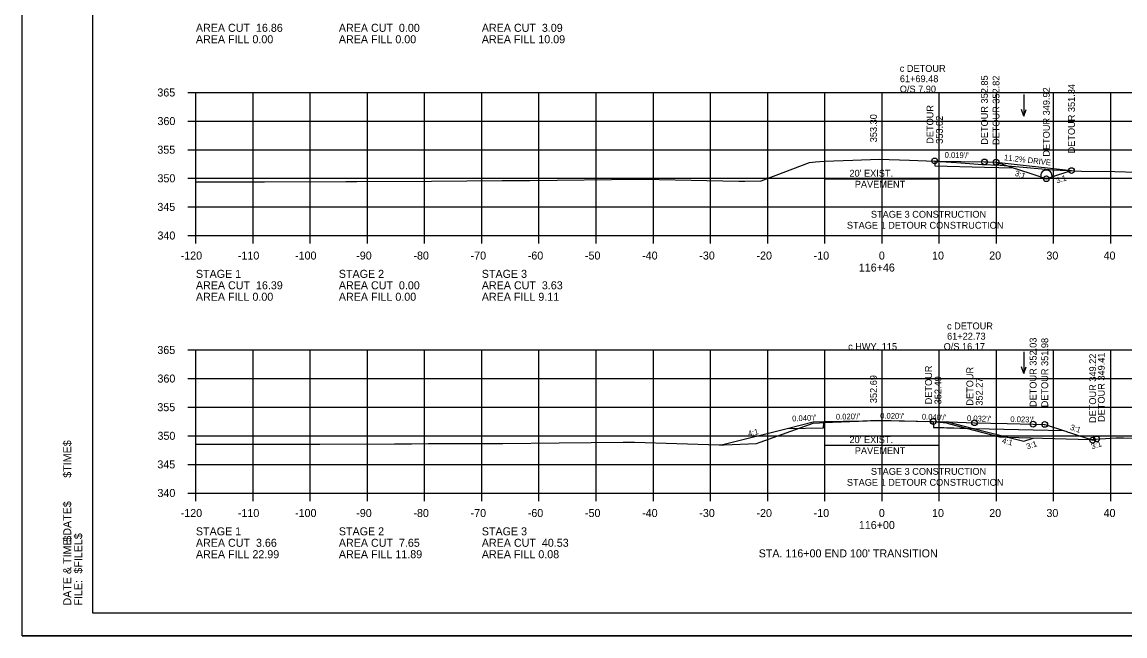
# Model space of a CAD drawing. Extents: x 1630712 to 1632516, y 782146 to 785403.
# Drawn here: x 1632182.6 to 1632375.4, y 785190 to 785297.3 of the extents above; entities that cross this region are included whole.
import ezdxf

# ---------------------------------------------------------------- set-up
doc = ezdxf.new("R2010")
doc.units = 0
for name, color, linetype in [('Default', 7, 'Continuous'), ('Notes', 7, 'Continuous'), ('R_Alt Surface', 7, 'Continuous'), ('R_Annot', 7, 'Continuous'), ('R_Axis', 7, 'Continuous'), ('R_Axis Annot', 7, 'Continuous'), ('R_Border', 7, 'Continuous'), ('R_Detour Subgrade', 7, 'Continuous'), ('R_Detour Surface', 7, 'Continuous'), ('R_Exist Surface', 7, 'Continuous'), ('R_Fin Surface', 7, 'Continuous'), ('R_Grid', 7, 'Continuous'), ('R_No Plot', 7, 'Continuous'), ('R_Water Annot', 7, 'Continuous'), ('R_Xsect Elev', 7, 'Continuous'), ('R_Xsect Elev Detour', 7, 'Continuous'), ('R_Xsect Slope', 7, 'Continuous')]:
    doc.layers.add(name, color=color, linetype=linetype)

msp = doc.modelspace()

# ---------------------------------------------------------------- linework, layer by layer
at = {"layer": 'Default'}
for centre, radius, start, end in [((1632361.69, 785270.42), 0.995, 356.5785, 183.4215), ((1632361.1, 785270.38), 0.412, 183.4215, 256.4158), ((1632362.27, 785270.38), 0.412, 283.5842, 356.5785), ((1632361.69, 785272.79), 2.89, 256.4158, 283.5842)]:
    msp.add_arc(centre, radius, start, end, dxfattribs=at)
at = {"layer": 'Notes'}
for p, q in [((1632322.96, 785268.2), (1632322.96, 785271.6)), ((1632342.96, 785268.2), (1632342.96, 785271.6)), ((1632322.96, 785269.9), (1632342.96, 785269.9)), ((1632322.96, 785221.64), (1632322.96, 785225.04)), ((1632342.96, 785221.64), (1632342.96, 785225.04)), ((1632322.96, 785223.34), (1632342.96, 785223.34))]:
    msp.add_line(p, q, dxfattribs=at)
at = {"layer": 'R_Alt Surface'}
msp.add_lwpolyline([(1632316.37, 785226.27), (1632322.7, 785226.39), (1632322.75, 785227.3), (1632330.92, 785227.64), (1632332.96, 785227.68), (1632341.91, 785227.48), (1632341.96, 785226.42), (1632348.87, 785226.28)], dxfattribs=at)
at = {"layer": 'R_Axis'}
for p, q in [((1632211.56, 785284.98), (1632212.96, 785284.98)), ((1632212.96, 785259.98), (1632212.96, 785284.98)), ((1632211.56, 785279.98), (1632212.96, 785279.98)), ((1632211.56, 785274.98), (1632212.96, 785274.98)), ((1632211.56, 785269.98), (1632212.96, 785269.98)), ((1632211.56, 785264.98), (1632212.96, 785264.98)), ((1632211.56, 785259.98), (1632212.96, 785259.98)), ((1632212.96, 785259.98), (1632492.96, 785259.98)), ((1632212.96, 785258.58), (1632212.96, 785259.98)), ((1632222.96, 785258.58), (1632222.96, 785259.98)), ((1632232.96, 785258.58), (1632232.96, 785259.98)), ((1632242.96, 785258.58), (1632242.96, 785259.98)), ((1632252.96, 785258.58), (1632252.96, 785259.98)), ((1632262.96, 785258.58), (1632262.96, 785259.98)), ((1632272.96, 785258.58), (1632272.96, 785259.98)), ((1632282.96, 785258.58), (1632282.96, 785259.98)), ((1632292.96, 785258.58), (1632292.96, 785259.98)), ((1632302.96, 785258.58), (1632302.96, 785259.98)), ((1632312.96, 785258.58), (1632312.96, 785259.98)), ((1632322.96, 785258.58), (1632322.96, 785259.98)), ((1632332.96, 785258.58), (1632332.96, 785259.98)), ((1632342.96, 785258.58), (1632342.96, 785259.98)), ((1632352.96, 785258.58), (1632352.96, 785259.98)), ((1632362.96, 785258.58), (1632362.96, 785259.98)), ((1632372.96, 785258.58), (1632372.96, 785259.98)), ((1632211.56, 785239.98), (1632212.96, 785239.98)), ((1632212.96, 785214.98), (1632212.96, 785239.98)), ((1632211.56, 785234.98), (1632212.96, 785234.98)), ((1632211.56, 785229.98), (1632212.96, 785229.98)), ((1632211.56, 785224.98), (1632212.96, 785224.98)), ((1632211.56, 785219.98), (1632212.96, 785219.98)), ((1632211.56, 785214.98), (1632212.96, 785214.98)), ((1632212.96, 785214.98), (1632492.96, 785214.98)), ((1632212.96, 785213.58), (1632212.96, 785214.98)), ((1632222.96, 785213.58), (1632222.96, 785214.98)), ((1632232.96, 785213.58), (1632232.96, 785214.98)), ((1632242.96, 785213.58), (1632242.96, 785214.98)), ((1632252.96, 785213.58), (1632252.96, 785214.98)), ((1632262.96, 785213.58), (1632262.96, 785214.98)), ((1632272.96, 785213.58), (1632272.96, 785214.98)), ((1632282.96, 785213.58), (1632282.96, 785214.98)), ((1632292.96, 785213.58), (1632292.96, 785214.98)), ((1632302.96, 785213.58), (1632302.96, 785214.98)), ((1632312.96, 785213.58), (1632312.96, 785214.98)), ((1632322.96, 785213.58), (1632322.96, 785214.98)), ((1632332.96, 785213.58), (1632332.96, 785214.98)), ((1632342.96, 785213.58), (1632342.96, 785214.98)), ((1632352.96, 785213.58), (1632352.96, 785214.98)), ((1632362.96, 785213.58), (1632362.96, 785214.98)), ((1632372.96, 785213.58), (1632372.96, 785214.98))]:
    msp.add_line(p, q, dxfattribs=at)
at = {"layer": 'R_Border'}
for p, q in [((1632194.96, 785193.98), (1632194.96, 785399.44)), ((1632511.14, 785193.98), (1632194.96, 785193.98))]:
    msp.add_line(p, q, dxfattribs=at)
at = {"layer": 'R_Detour Subgrade'}
for points in [[(1632342.16, 785273.01), (1632342.17, 785272.13), (1632350.87, 785271.94), (1632355.86, 785271.82)], [(1632342.16, 785273.01), (1632342.17, 785272.13), (1632350.87, 785271.94), (1632355.86, 785271.82)], [(1632341.91, 785227.48), (1632341.96, 785226.48), (1632349.13, 785226.25), (1632359.37, 785226.01), (1632364.68, 785225.89)], [(1632341.91, 785227.48), (1632341.96, 785226.48), (1632349.13, 785226.25), (1632359.37, 785226.01), (1632364.68, 785225.89)]]:
    msp.add_lwpolyline(points, dxfattribs=at)
at = {"layer": 'R_Detour Surface'}
msp.add_line((1632352.89, 785272.8), (1632366.08, 785271.33), dxfattribs=at)
for points in [[(1632342.16, 785273.01), (1632342.16, 785273.01), (1632342.58, 785273), (1632350.87, 785272.84), (1632351.39, 785272.83), (1632352.89, 785272.8), (1632354.74, 785272.19), (1632355.86, 785271.82), (1632356.24, 785271.7), (1632356.47, 785271.62), (1632359.33, 785270.68), (1632361.69, 785269.9), (1632363.55, 785270.51), (1632366.07, 785271.33)], [(1632341.91, 785227.48), (1632344.71, 785227.39), (1632349.12, 785227.25), (1632349.12, 785227.25), (1632349.13, 785227.25), (1632354.84, 785227.12), (1632359.37, 785227.01), (1632361.33, 785226.96), (1632361.41, 785226.96), (1632361.82, 785226.83), (1632364.68, 785225.89), (1632365.25, 785225.7), (1632365.3, 785225.68), (1632365.73, 785225.54), (1632369.79, 785224.21), (1632370.29, 785224.37), (1632370.38, 785224.4)]]:
    msp.add_lwpolyline(points, dxfattribs=at)
at = {"layer": 'R_Exist Surface'}
for points in [[(1632212.96, 785269.38), (1632215.02, 785269.38), (1632224.55, 785269.39), (1632224.96, 785269.39), (1632239.16, 785269.4), (1632241.1, 785269.42), (1632254.16, 785269.5), (1632266.5, 785269.58), (1632271.36, 785269.6), (1632290.42, 785269.83), (1632293.98, 785269.76), (1632307.93, 785269.46), (1632308.96, 785269.48), (1632311.81, 785269.55), (1632314.42, 785270.55), (1632320.26, 785272.75), (1632321.33, 785272.84), (1632322.83, 785272.95), (1632327.83, 785273.13), (1632332.43, 785273.3), (1632337.77, 785273.14), (1632342.16, 785273), (1632346, 785272.72), (1632350.51, 785272.38), (1632353.59, 785272.25), (1632357.63, 785271.9), (1632362.85, 785271.45), (1632367.86, 785271.25), (1632373.64, 785271.16), (1632385.05, 785270.84)], [(1632212.96, 785223.49), (1632216.29, 785223.5), (1632218.87, 785223.49), (1632232.02, 785223.54), (1632234.66, 785223.54), (1632247.72, 785223.58), (1632250.65, 785223.6), (1632253.62, 785223.61), (1632266.63, 785223.66), (1632276.46, 785223.76), (1632287.69, 785223.84), (1632289.65, 785223.86), (1632304.45, 785223.42), (1632305.12, 785223.41), (1632305.37, 785223.41), (1632311.01, 785223.62), (1632311.66, 785223.85), (1632320.9, 785227.21), (1632322.02, 785227.27), (1632322.75, 785227.3), (1632331.85, 785227.67), (1632332.27, 785227.69), (1632341.48, 785227.49), (1632341.91, 785227.48), (1632344.21, 785227.22), (1632344.39, 785227.2), (1632344.78, 785227.09), (1632353.47, 785224.8), (1632354.82, 785224.71), (1632369.32, 785224.33), (1632372.96, 785224.55), (1632373.88, 785224.61), (1632375.2, 785224.6), (1632397.58, 785224.46)]]:
    msp.add_lwpolyline(points, dxfattribs=at)
at = {"layer": 'R_Fin Surface'}
msp.add_lwpolyline([(1632304.95, 785223.41), (1632304.97, 785223.4), (1632305.11, 785223.45), (1632316.37, 785226.27), (1632320.9, 785227.4), (1632322.75, 785227.47), (1632332.96, 785227.68), (1632341.9, 785227.5), (1632344.39, 785227.4), (1632348.87, 785226.28), (1632357.76, 785224.06), (1632359.37, 785224.59)], dxfattribs=at)
at = {"layer": 'R_Grid'}
for p, q in [((1632212.96, 785284.98), (1632492.96, 785284.98)), ((1632212.96, 785259.98), (1632212.96, 785284.98)), ((1632222.96, 785259.98), (1632222.96, 785284.98)), ((1632232.96, 785259.98), (1632232.96, 785284.98)), ((1632242.96, 785259.98), (1632242.96, 785284.98)), ((1632252.96, 785259.98), (1632252.96, 785284.98)), ((1632262.96, 785259.98), (1632262.96, 785284.98)), ((1632272.96, 785259.98), (1632272.96, 785284.98)), ((1632282.96, 785259.98), (1632282.96, 785284.98)), ((1632292.96, 785259.98), (1632292.96, 785284.98)), ((1632302.96, 785259.98), (1632302.96, 785284.98)), ((1632312.96, 785259.98), (1632312.96, 785284.98)), ((1632322.96, 785259.98), (1632322.96, 785284.98)), ((1632332.96, 785259.98), (1632332.96, 785284.98)), ((1632342.96, 785259.98), (1632342.96, 785284.98)), ((1632352.96, 785259.98), (1632352.96, 785284.98)), ((1632362.96, 785259.98), (1632362.96, 785284.98)), ((1632372.96, 785259.98), (1632372.96, 785284.98)), ((1632212.96, 785279.98), (1632492.96, 785279.98)), ((1632212.96, 785274.98), (1632492.96, 785274.98)), ((1632212.96, 785269.98), (1632492.96, 785269.98)), ((1632212.96, 785264.98), (1632492.96, 785264.98)), ((1632212.96, 785259.98), (1632492.96, 785259.98)), ((1632212.96, 785239.98), (1632492.96, 785239.98)), ((1632212.96, 785214.98), (1632212.96, 785239.98)), ((1632222.96, 785214.98), (1632222.96, 785239.98)), ((1632232.96, 785214.98), (1632232.96, 785239.98)), ((1632242.96, 785214.98), (1632242.96, 785239.98)), ((1632252.96, 785214.98), (1632252.96, 785239.98)), ((1632262.96, 785214.98), (1632262.96, 785239.98)), ((1632272.96, 785214.98), (1632272.96, 785239.98)), ((1632282.96, 785214.98), (1632282.96, 785239.98)), ((1632292.96, 785214.98), (1632292.96, 785239.98)), ((1632302.96, 785214.98), (1632302.96, 785239.98)), ((1632312.96, 785214.98), (1632312.96, 785239.98)), ((1632322.96, 785214.98), (1632322.96, 785239.98)), ((1632332.96, 785214.98), (1632332.96, 785239.98)), ((1632342.96, 785214.98), (1632342.96, 785239.98)), ((1632352.96, 785214.98), (1632352.96, 785239.98)), ((1632362.96, 785214.98), (1632362.96, 785239.98)), ((1632372.96, 785214.98), (1632372.96, 785239.98)), ((1632212.96, 785234.98), (1632492.96, 785234.98)), ((1632212.96, 785229.98), (1632492.96, 785229.98)), ((1632212.96, 785224.98), (1632492.96, 785224.98)), ((1632212.96, 785219.98), (1632492.96, 785219.98)), ((1632212.96, 785214.98), (1632492.96, 785214.98))]:
    msp.add_line(p, q, dxfattribs=at)
at = {"layer": 'R_No Plot'}
msp.add_line((1632182.56, 785190), (1632515.9, 785190), dxfattribs=at)
msp.add_lwpolyline([(1632182.56, 785403.34), (1632515.9, 785403.34), (1632515.9, 785190), (1632182.56, 785190)], close=True, dxfattribs=at)
for centre in [(1632342.16, 785273.01), (1632350.87, 785272.84), (1632352.89, 785272.8), (1632361.69, 785269.9), (1632366.08, 785271.33), (1632341.91, 785227.48), (1632349.13, 785227.25), (1632359.37, 785227.01), (1632361.41, 785226.96), (1632369.79, 785224.21), (1632370.48, 785224.43)]:
    msp.add_circle(centre, 0.5, dxfattribs=at)
at = {"layer": 'R_Water Annot'}
for p, q in [((1632357.76, 785284.63), (1632357.76, 785280.86)), ((1632357.76, 785280.86), (1632357.34, 785282.02)), ((1632357.76, 785280.86), (1632358.18, 785282.02)), ((1632357.76, 785239.63), (1632357.76, 785235.86)), ((1632357.76, 785235.86), (1632357.34, 785237.02)), ((1632357.76, 785235.86), (1632358.18, 785237.02))]:
    msp.add_line(p, q, dxfattribs=at)

# ---------------------------------------------------------------- texts
at = {"layer": 'Default'}
for s, height, p in [('$TIME$', 1.397, (1632191.16, 785217.65)), ('$DATE$', 1.397, (1632191.16, 785206.48)), ('DATE & TIME:', 1.3968, (1632191.16, 785195.31)), ('$FILEL$', 1.397, (1632193.08, 785200.89)), ('FILE: ', 1.397, (1632193.08, 785195.31))]:
    msp.add_text(s, height=height, rotation=90, dxfattribs=at).set_placement(p)
at = {"layer": 'Notes'}
for s, p in [('c DETOUR', (1632336.05, 785288.58)), ('61+69.48', (1632336.07, 785286.78)), ('O/S 7.90', (1632336.06, 785284.98)), ("20' EXIST.", (1632327.26, 785270.26)), ('PAVEMENT', (1632328.19, 785268.34)), ('STAGE 3 CONSTRUCTION', (1632331.01, 785263.09)), ('STAGE 1 DETOUR CONSTRUCTION', (1632326.81, 785261.17)), ('c DETOUR', (1632344.32, 785243.58)), ('c HWY. 115', (1632327.02, 785239.98)), ('O/S 16.17', (1632343.73, 785239.98)), ('61+22.73', (1632344.33, 785241.78)), ("20' EXIST.", (1632327.26, 785223.7)), ('PAVEMENT', (1632328.19, 785221.78)), ('STAGE 3 CONSTRUCTION', (1632331.01, 785218.16)), ('STAGE 1 DETOUR CONSTRUCTION', (1632326.81, 785216.24))]:
    msp.add_text(s, height=1.2, dxfattribs=at).set_placement(p)
msp.add_text('11.2% DRIVE', height=1, rotation=353.636, dxfattribs=at).set_placement((1632354.24, 785273.14))
at = {"layer": 'R_Annot'}
msp.add_text("STA. 116+00 END 100' TRANSITION", height=1.4, dxfattribs=at).set_placement((1632311.38, 785203.73))
at = {"layer": 'R_Axis'}
for p in [(1632212.96, 785259.98), (1632212.96, 785214.98)]:
    msp.add_text('-', height=0.0001, dxfattribs=at).set_placement(p)
at = {"layer": 'R_Axis Annot'}
for s, p in [('AREA CUT  16.86', (1632212.96, 785295.58)), ('AREA CUT  0.00', (1632237.96, 785295.58)), ('AREA CUT  3.09', (1632262.96, 785295.58)), ('AREA FILL 0.00', (1632212.96, 785293.58)), ('AREA FILL 0.00', (1632237.96, 785293.58)), ('AREA FILL 10.09', (1632262.96, 785293.58)), ('365', (1632206.22, 785284.28)), ('360', (1632206.24, 785279.28)), ('355', (1632206.22, 785274.28)), ('350', (1632206.24, 785269.28)), ('345', (1632206.22, 785264.28)), ('340', (1632206.24, 785259.28)), ('-120', (1632210.3, 785255.78)), ('-110', (1632220.3, 785255.78)), ('-100', (1632230.3, 785255.78)), ('-90', (1632241, 785255.78)), ('-80', (1632251, 785255.78)), ('-70', (1632261, 785255.78)), ('-60', (1632271, 785255.78)), ('-50', (1632281, 785255.78)), ('-40', (1632291, 785255.78)), ('-30', (1632301, 785255.78)), ('-20', (1632311, 785255.78)), ('-10', (1632321, 785255.78)), ('0', (1632332.4, 785255.78)), ('10', (1632341.7, 785255.78)), ('20', (1632351.7, 785255.78)), ('30', (1632361.7, 785255.78)), ('40', (1632371.7, 785255.78)), ('116+46', (1632328.89, 785253.68)), ('STAGE 1', (1632212.96, 785252.58)), ('STAGE 2', (1632237.96, 785252.58)), ('STAGE 3', (1632262.96, 785252.58)), ('AREA CUT  16.39', (1632212.96, 785250.58)), ('AREA CUT  0.00', (1632237.96, 785250.58)), ('AREA CUT  3.63', (1632262.96, 785250.58)), ('AREA FILL 0.00', (1632212.96, 785248.58)), ('AREA FILL 0.00', (1632237.96, 785248.58)), ('AREA FILL 9.11', (1632262.96, 785248.58)), ('365', (1632206.22, 785239.28)), ('360', (1632206.24, 785234.28)), ('355', (1632206.22, 785229.28)), ('350', (1632206.24, 785224.28)), ('345', (1632206.22, 785219.28)), ('340', (1632206.24, 785214.28)), ('-120', (1632210.3, 785210.78)), ('-110', (1632220.3, 785210.78)), ('-100', (1632230.3, 785210.78)), ('-90', (1632241, 785210.78)), ('-80', (1632251, 785210.78)), ('-70', (1632261, 785210.78)), ('-60', (1632271, 785210.78)), ('-50', (1632281, 785210.78)), ('-40', (1632291, 785210.78)), ('-30', (1632301, 785210.78)), ('-20', (1632311, 785210.78)), ('-10', (1632321, 785210.78)), ('0', (1632332.4, 785210.78)), ('10', (1632341.7, 785210.78)), ('20', (1632351.7, 785210.78)), ('30', (1632361.7, 785210.78)), ('40', (1632371.7, 785210.78)), ('STAGE 1', (1632212.96, 785207.58)), ('STAGE 2', (1632237.96, 785207.58)), ('STAGE 3', (1632262.96, 785207.58)), ('116+00', (1632328.9, 785208.68)), ('AREA CUT  3.66', (1632212.96, 785205.58)), ('AREA CUT  7.65', (1632237.96, 785205.58)), ('AREA CUT  40.53', (1632262.96, 785205.58)), ('AREA FILL 22.99', (1632212.96, 785203.58)), ('AREA FILL 11.89', (1632237.96, 785203.58)), ('AREA FILL 0.08', (1632262.96, 785203.58))]:
    msp.add_text(s, height=1.4, dxfattribs=at).set_placement(p)
at = {"layer": 'R_Xsect Elev'}
for s, p in [('353.30', (1632332.06, 785276.28)), ('352.69', (1632332.06, 785230.68))]:
    msp.add_text(s, height=1.2, rotation=90, dxfattribs=at).set_placement(p)
at = {"layer": 'R_Xsect Elev Detour'}
for s, p in [('DETOUR 352.85', (1632351.47, 785275.84)), ('DETOUR 352.82', (1632353.49, 785275.8)), ('DETOUR 349.92', (1632362.29, 785273.76)), ('DETOUR 351.34', (1632366.68, 785274.33)), ('DETOUR', (1632341.94, 785276.01)), ('353.02', (1632343.59, 785276.01)), ('DETOUR 352.03', (1632359.97, 785230.01)), ('DETOUR 351.98', (1632362.01, 785229.96)), ('DETOUR 349.22', (1632370.39, 785227.21)), ('DETOUR 349.41', (1632371.9, 785227.4)), ('DETOUR', (1632341.68, 785230.48)), ('DETOUR', (1632348.91, 785230.25)), ('352.49', (1632343.33, 785230.48)), ('352.27', (1632350.56, 785230.25))]:
    msp.add_text(s, height=1.2, rotation=90, dxfattribs=at).set_placement(p)
at = {"layer": 'R_Xsect Slope'}
for s, rotation, p in [("0.019'/'", 358.8884, (1632343.89, 785273.57)), ('3:1', 341.7824, (1632356.1, 785270.46)), ('3:1', 17.9815, (1632363.55, 785269.07)), ("0.040'/'", 2.2906, (1632317.25, 785227.49)), ("0.020'/'", 1.1458, (1632324.88, 785227.81)), ("0.020'/'", 358.8542, (1632332.61, 785228)), ("0.040'/'", 357.7094, (1632339.9, 785227.83)), ("0.032'/'", 358.1948, (1632347.79, 785227.56)), ("0.023'/'", 358.661, (1632355.38, 785227.4)), ('4:1', 14.0362, (1632309.64, 785224.84)), ('3:1', 341.7852, (1632365.76, 785226.06)), ('4:1', 345.9638, (1632353.87, 785223.7)), ('3:1', 18.4349, (1632358.39, 785222.6)), ('3:1', 18.4349, (1632369.7, 785222.6))]:
    msp.add_text(s, height=1, rotation=rotation, dxfattribs=at).set_placement(p)

doc.saveas('drawing.dxf')
